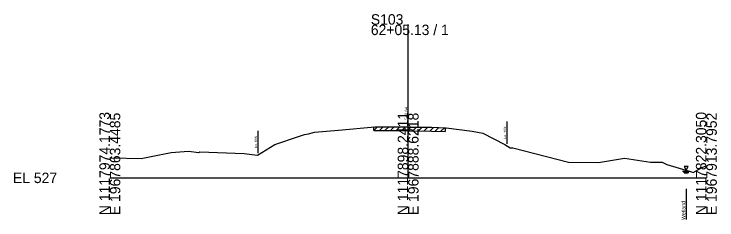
# Model space of a CAD drawing. Extents: x -26 to 163, y -10 to 24018.
# Drawn here: x -25.7 to 162.8, y 9988.7 to 10044 of the extents above; entities that cross this region are included whole.
import ezdxf

# ---------------------------------------------------------------- set-up
doc = ezdxf.new("R2010")
doc.units = 0
for name, color, linetype in [('RD_GPK_XS_Cell', 7, 'Continuous'), ('RD_XS_ExGround', 7, 'Continuous'), ('RD_XS_ExPaveRet', 7, 'Continuous'), ('RD_XS_ExRW', 7, 'Continuous'), ('RD_XS_EXWetland', 7, 'Continuous'), ('RD_XS_TX_Elev_EX', 7, 'Continuous')]:
    doc.layers.add(name, color=color, linetype=linetype)

msp = doc.modelspace()

# ---------------------------------------------------------------- linework, layer by layer
at = {"layer": 'RD_GPK_XS_Cell'}
for p, q in [((80, 10000), (80, 10041.11)), ((0, 10000), (80, 10000)), ((80, 10000), (160, 10000))]:
    msp.add_line(p, q, dxfattribs=at)
at = {"layer": 'RD_XS_ExGround'}
msp.add_lwpolyline([(0, 10005.4), (0.45, 10005.39), (8.43, 10005.23), (16.42, 10006.78), (21.1, 10007.15), (23.83, 10006.83), (24.13, 10006.95), (36.03, 10006.53), (39.6, 10006.05), (44.22, 10008.97), (50.62, 10011.12), (52.23, 10011.65), (53.32, 10011.84), (54.9, 10012.3), (61.33, 10012.8), (71.07, 10013.7), (76.16, 10013.7), (79.68, 10013.67), (80, 10013.64), (86.26, 10013.56), (90.22, 10013.45), (97.18, 10012.52), (100.08, 10011.99), (105.97, 10008.93), (107.37, 10008.1), (108.07, 10008.04), (123.05, 10004.25), (131.1, 10004.1), (138.04, 10005.26), (145.06, 10004.24), (148.14, 10004.17), (149.4, 10003.61), (156.02, 10001.64), (156.49, 10001.48), (158.52, 10002.58), (160, 10003.28)], dxfattribs=at)
at = {"layer": 'RD_XS_ExPaveRet'}
for p, q in [((70.79, 10012.68), (71.82, 10013.7)), ((70.79, 10012.68), (70.79, 10013.68)), ((72.29, 10012.7), (73.29, 10013.7)), ((73.79, 10012.7), (74.79, 10013.7)), ((75.29, 10012.7), (76.29, 10013.7)), ((76.79, 10012.69), (77.78, 10013.69)), ((78.29, 10012.68), (79.28, 10013.67)), ((79.79, 10012.66), (80.76, 10013.63)), ((81.29, 10012.62), (82.28, 10013.61)), ((82.79, 10012.6), (83.78, 10013.59)), ((84.29, 10012.58), (85.28, 10013.57)), ((85.79, 10012.56), (86.77, 10013.54)), ((87.29, 10012.53), (88.27, 10013.5)), ((88.79, 10012.49), (89.77, 10013.46)), ((89.92, 10013.45), (89.92, 10012.45)), ((70.79, 10012.68), (71.07, 10012.7)), ((71.07, 10012.7), (76.16, 10012.7)), ((76.16, 10012.7), (79.68, 10012.67)), ((79.68, 10012.67), (80, 10012.64)), ((80, 10012.64), (86.26, 10012.56)), ((86.26, 10012.56), (89.92, 10012.45))]:
    msp.add_line(p, q, dxfattribs=at)
at = {"layer": 'RD_XS_ExRW'}
for p, q in [((106.49, 10015.12), (106.49, 10009.12)), ((39.71, 10012.62), (39.71, 10006.62))]:
    msp.add_line(p, q, dxfattribs=at)
at = {"layer": 'RD_XS_EXWetland'}
for p, q in [((153.59, 10001.82), (155.59, 10001.82)), ((154.09, 10003.07), (154.59, 10002.07)), ((155.09, 10003.07), (154.09, 10003.07)), ((154.59, 10002.07), (155.09, 10003.07)), ((153.84, 10001.57), (155.34, 10001.57)), ((154.09, 10001.32), (155.09, 10001.32)), ((154.59, 9997.07), (154.59, 9988.82))]:
    msp.add_line(p, q, dxfattribs=at)

# ---------------------------------------------------------------- texts
at = {"layer": 'RD_GPK_XS_Cell'}
for s, p in [('S103', (70, 10041.11)), ('62+05.13 / 1', (70, 10038.31)), ('EL 527', (-26, 9998.6))]:
    msp.add_text(s, height=2.8, dxfattribs=at).set_placement(p)
for s, p in [('N 1117974.1773', (0, 9990)), ('E 1967863.4485', (2.8, 9990)), ('N 1117898.2411', (80, 9990)), ('E 1967888.6218', (82.8, 9990)), ('N 1117822.3050', (160, 9990)), ('E 1967913.7952', (162.8, 9990))]:
    msp.add_text(s, height=2.8, rotation=90, dxfattribs=at).set_placement(p)
at = {"layer": 'RD_XS_ExRW'}
for p in [(106.24, 10010.47), (39.46, 10007.97)]:
    msp.add_text('Ex. R/W ', height=0.65, rotation=90, dxfattribs=at).set_placement(p)
at = {"layer": 'RD_XS_EXWetland'}
msp.add_text('Wetland ', height=1, rotation=90, dxfattribs=at).set_placement((154.34, 9988.71))
at = {"layer": 'RD_XS_TX_Elev_EX'}
msp.add_text('540.64', height=0.8, rotation=90, dxfattribs=at).set_placement((79.9, 10015.64))

doc.saveas('drawing.dxf')
